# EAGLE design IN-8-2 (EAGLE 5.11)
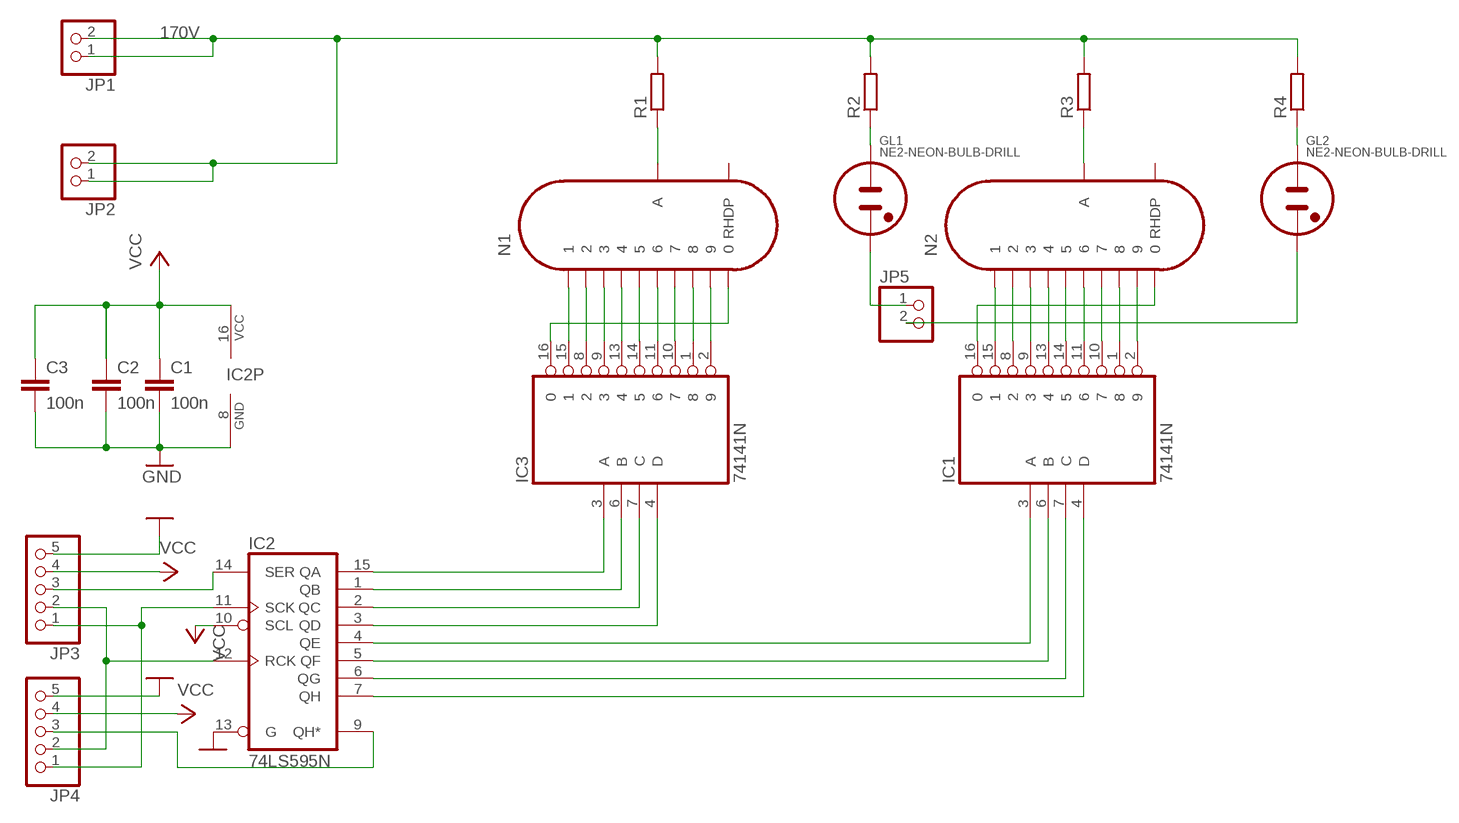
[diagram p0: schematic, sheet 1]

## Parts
C1  100n  C-EU025_050-025X075  [C025_050-025X075]
C2  100n  C-EU025_050-025X075  [C025_050-025X075]
C3  100n  C-EU025_050-025X075  [C025_050-025X075]
GL1  NE2-NEON-BULB-DRILL  [NE2-NEON-BULB-DRILL]
GL2  NE2-NEON-BULB-DRILL  [NE2-NEON-BULB-DRILL]
IC1  74141N  [DIL16]
IC2  74LS595N  [DIL16]
IC3  74141N  [DIL16]
JP1  PINHD-1X2  [1X02]
JP2  PINHD-1X2  [1X02]
JP3  PINHD-1X5  [1X05]
JP4  PINHD-1X5  [1X05]
JP5  PINHD-1X2  [1X02]
N1  IN-8-2  [IN-8-2]
N2  IN-8-2  [IN-8-2]
R1  R-EU_0207/12  [0207/12]
R2  R-EU_0207/12  [0207/12]
R3  R-EU_0207/12  [0207/12]
R4  R-EU_0207/12  [0207/12]

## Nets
170V: JP1.1 JP1.2 JP2.1 JP2.2 R1.2 R2.2 R3.2 R4.2
GND: C1.2 C2.2 C3.2 IC2.8(GND) IC2.13(G) JP3.5 JP4.5
N$1: IC3.15 N1.1
N$2: IC3.8 N1.2
N$3: IC3.9 N1.3
N$4: IC3.13 N1.4
N$5: IC3.14 N1.5
N$6: IC3.11 N1.6
N$7: IC3.10 N1.7
N$8: IC3.1 N1.8
N$9: IC3.2 N1.9
N$10: IC3.16 N1.0
N$11: N1.A R1.1
N$12: GL1.1(A) R2.1
N$13: IC1.15 N2.1
N$15: IC1.8 N2.2
N$16: IC1.9 N2.3
N$17: IC1.13 N2.4
N$18: IC1.14 N2.5
N$19: IC1.11 N2.6
N$20: IC1.10 N2.7
N$21: IC1.1 N2.8
N$22: IC1.2 N2.9
N$23: IC1.16 N2.0
N$25: N2.A R3.1
N$26: GL2.1(A) R4.1
N$27: GL1.2(A1) JP5.1
N$28: IC2.15(QA) IC3.3(A)
N$29: IC2.1(QB) IC3.6(B)
N$30: IC2.2(QC) IC3.7(C)
N$31: IC2.3(QD) IC3.4(D)
N$32: IC1.3(A) IC2.4(QE)
N$33: IC1.6(B) IC2.5(QF)
N$34: IC1.7(C) IC2.6(QG)
N$35: IC1.4(D) IC2.7(QH)
N$37: GL2.2(A1) JP5.2
N$40: IC2.14(SER) JP3.3
N$41: IC2.11(SCK) JP3.1 JP4.1
N$42: IC2.12(RCK) JP3.2 JP4.2
N$45: IC2.9(QH*) JP4.3
VCC: C1.1 C2.1 C3.1 IC2.10(SCL) IC2.16(VCC) JP3.4 JP4.4
Unconnected: N1..(RHDP) N2..(RHDP)

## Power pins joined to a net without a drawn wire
GND: IC1.12(GND) IC3.12(GND)
VCC: IC1.5(VCC) IC3.5(VCC)

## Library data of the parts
C1-C3 = resistor:C-EU: CAPACITOR, European symbol
GL1 GL2 = nixies:NE2-NEON-BULB: Neon indicator (wire connection)
IC1 IC3 = 74xx-eu:74*141: BCD to decimal DECODER/DRIVER
IC2 = 74xx-us:74*595: 8-bit SHIFT REGISTER, output latch
JP1 JP2 JP5 = pinhead:PINHD-1X2: PIN HEADER
JP3 JP4 = pinhead:PINHD-1X5: PIN HEADER
N1 N2 = russian-nixies:IN-8-2: IN-8-2: medium numeric frontview nixie tube
R1-R4 = resistor:R-EU_: RESISTOR, European symbol

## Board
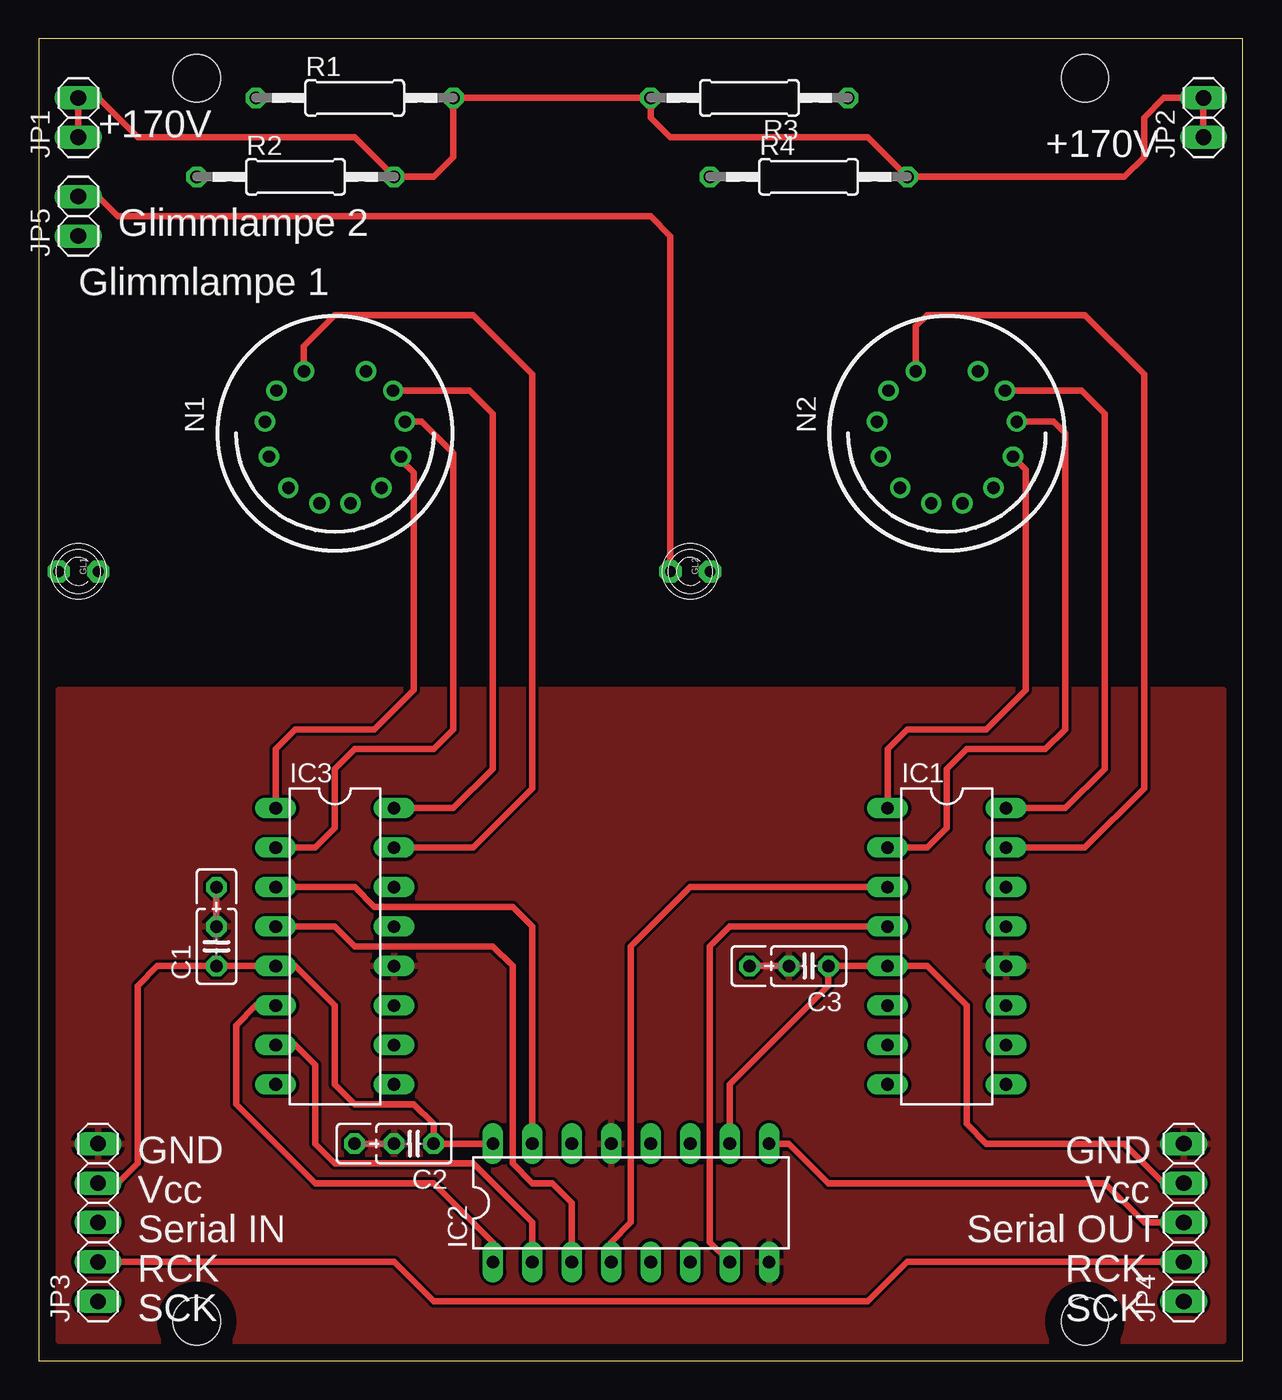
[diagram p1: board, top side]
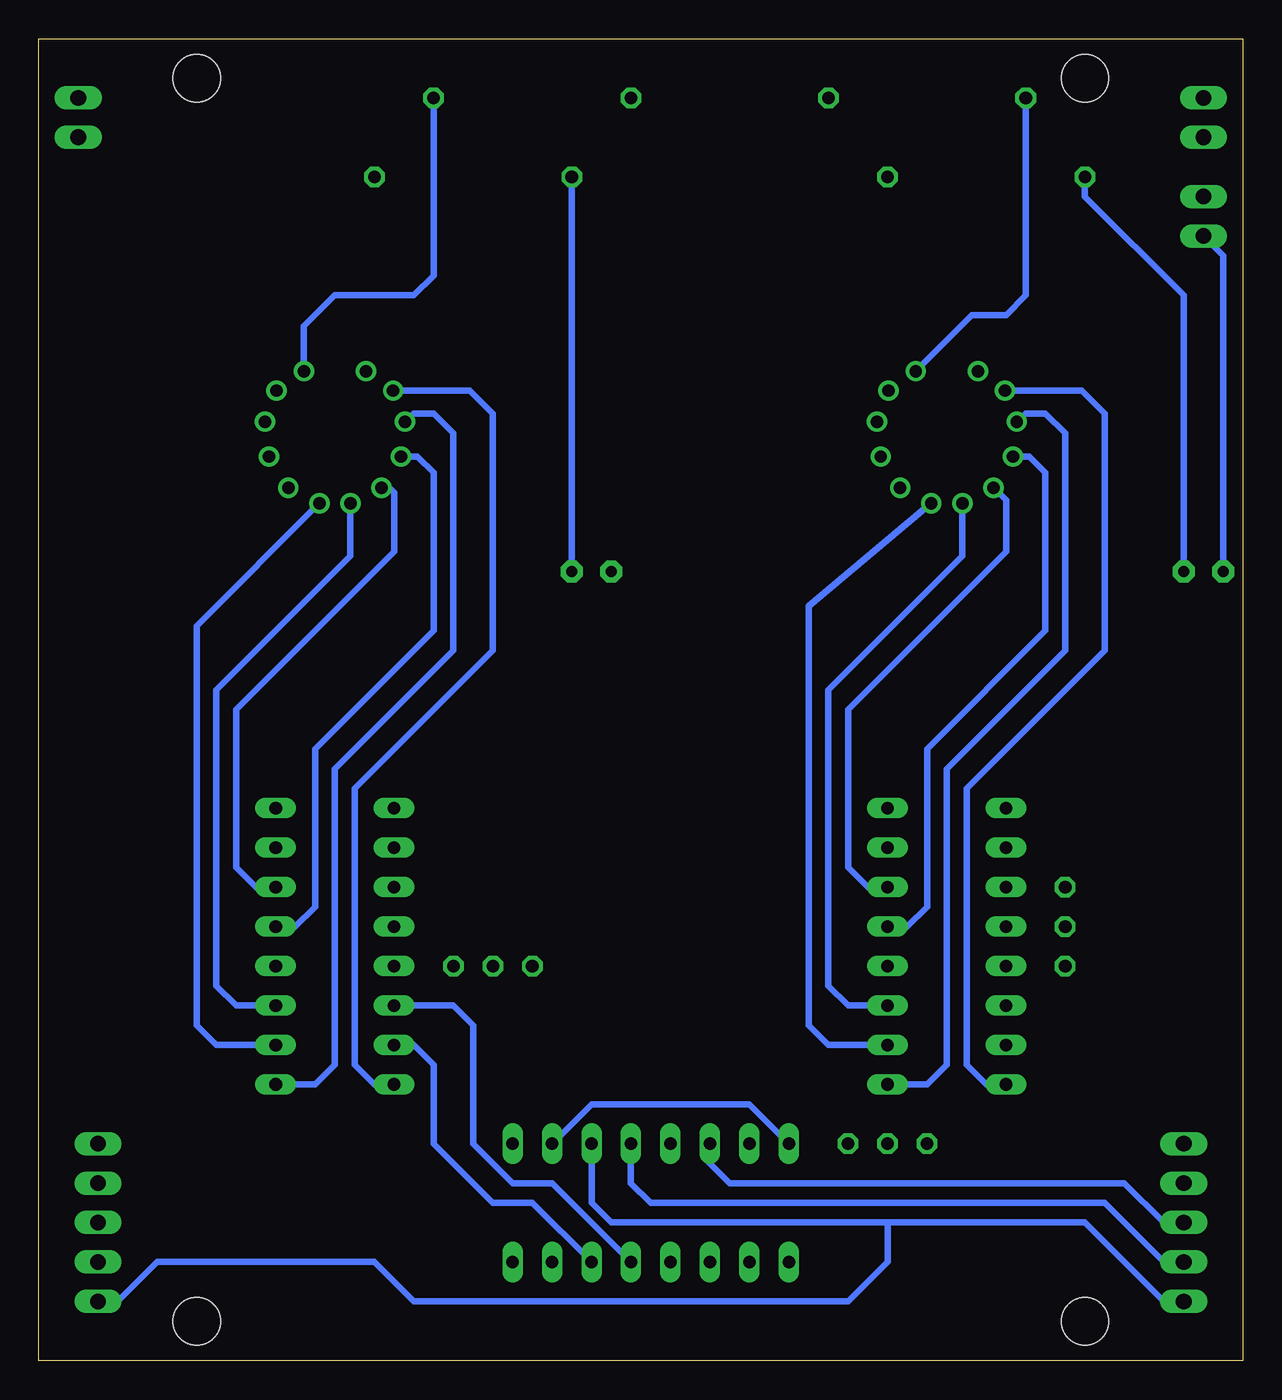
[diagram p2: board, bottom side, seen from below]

Size 77.47 x 85.08 mm. Coordinates in mm from the lower left corner, seen from the top.
Outline: 0,0 77.47,0 77.47,85.08 0,85.08 0,0
Copper layers (1*16): Top 0.035mm / dielectric 1.5mm / Bottom 0.035mm
Design rules "default": minimum track width 10mil, minimum drill 24mil, track to track 8mil, track to pad 8mil, pad to pad 8mil, via to via 8mil, smd to smd 8mil, copper to edge 40mil, drill to drill 8mil, minimum pad ring 10mil, minimum via ring 8mil, stop-mask expansion 4mil, vias tented up to drill 0mil, thermal gap 10mil
Holes 3.05 mm at 10.16,82.55 67.31,82.55 67.31,2.54 10.16,2.54

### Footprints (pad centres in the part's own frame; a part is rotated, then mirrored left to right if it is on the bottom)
C025_050-025X075 = drill 0.813 octagon: 1 -1.27,0; 2 1.27,0; 3 3.81,0
NE2-NEON-BULB-DRILL = drill 0.7 pad 1.422 octagon: 1 0,1.27; 2 0,-1.27
DIL16 = drill 0.813 long: 1 -8.89,-3.81; 2 -6.35,-3.81; 3 -3.81,-3.81; 4 -1.27,-3.81; 5 1.27,-3.81; 6 3.81,-3.81; 7 6.35,-3.81; 8 8.89,-3.81; 9 8.89,3.81; 10 6.35,3.81; 11 3.81,3.81; 12 1.27,3.81; 13 -1.27,3.81; 14 -3.81,3.81; 15 -6.35,3.81; 16 -8.89,3.81
1X02 = drill 1.016 long: 1 -1.27,0; 2 1.27,0
1X05 = drill 1.016 long: 1 -5.08,0; 2 -2.54,0; 3 0,0; 4 2.54,0; 5 5.08,0
IN-8-2 = drill 0.8 round: 0 -3.75,-2.75; 1 2,-4; 2 3.75,-2.75; 3 4.5,-0.75; 4 4.25,1.5; 5 3,3.5; 6 1,4.5; 7 -1,4.5; 8 -4.25,1.5; 9 -4.5,-0.75; . -3,3.5; A -2,-4
0207/12 = drill 0.813 octagon: 1 -6.35,0; 2 6.35,0

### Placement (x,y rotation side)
C1  11.43,26.67 90 top
C2  24.13,13.97 180 top
C3  49.53,25.4 180 top
GL1  2.54,50.8 270 top
GL2  41.91,50.8 270 top
IC1  58.42,26.67 270 top
IC2  38.1,10.16 0 top
IC3  19.05,26.67 270 top
JP1  2.54,80.01 90 top
JP2  74.93,80.01 90 top
JP3  3.81,8.89 90 top
JP4  73.66,8.89 90 top
JP5  2.54,73.66 90 top
N1  19.05,59.69 180 top
N2  58.42,59.69 180 top
R1  20.32,81.28 0 top
R2  16.51,76.2 0 top
R3  45.72,81.28 180 top
R4  49.53,76.2 0 top

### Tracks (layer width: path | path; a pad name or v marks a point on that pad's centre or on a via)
170V
  Top 0.406: JP1.1 JP1.2 3.81,81.28 6.35,78.74 20.32,78.74 R2.2 25.4,76.2 26.67,77.47 R1.2 R3.2 39.37,80.01 40.64,78.74 53.34,78.74 R4.2 69.85,76.2 71.12,77.47 71.12,80.01 72.39,81.28 JP2.2 JP2.1
GND
  Top 0.406: 20.32,13.97 C2.2 | 45.72,25.4 C3.2 | C1.2 11.43,30.48
  pour Top: 1.27,43.18 76.2,43.18 76.2,1.27 1.27,1.27
N$1
  Top 0.406: N1.1 17.05,65.31 19.05,67.31 27.94,67.31 31.75,63.5 31.75,36.83 27.94,33.02 IC3.15
N$2
  Bottom 0.406: IC3.8 16.51,17.78 17.78,19.05 17.78,36.83 8.89,45.72 8.89,60.96 10.37,62.44 N1.2
N$3
  Bottom 0.406: IC3.9 20.32,17.78 19.05,19.05 19.05,38.1 11.43,45.72 11.43,59.69 12.7,60.96 13.97,60.96 14.49,60.44 N1.3
N$4
  Bottom 0.406: IC3.13 21.59,27.94 20.32,29.21 20.32,39.37 12.7,46.99 12.7,57.15 13.74,58.19 N1.4
N$5
  Bottom 0.406: IC3.14 24.13,30.48 25.4,31.75 25.4,41.91 15.24,52.07 15.24,55.38 N1.5
N$6
  Bottom 0.406: N1.6 18.05,51.8 26.67,43.18 26.67,24.13 25.4,22.86 IC3.11
N$7
  Bottom 0.406: IC3.10 26.67,20.32 27.94,21.59 27.94,48.57 N1.7
N$8
  Top 0.406: N1.8 23.3,57.98 24.13,57.15 24.13,43.18 21.59,40.64 16.51,40.64 15.24,39.37 IC3.1
N$9
  Top 0.406: N1.9 24.65,60.44 26.67,58.42 26.67,40.64 25.4,39.37 20.32,39.37 19.05,38.1 19.05,34.29 17.78,33.02 IC3.2
N$10
  Top 0.406: IC3.16 26.67,35.56 29.21,38.1 29.21,60.96 27.73,62.44 N1.0
N$11
  Bottom 0.406: R1.1 13.97,68.58 15.24,67.31 17.43,67.31 N1.A
N$12
  Bottom 0.406: R2.1 10.16,74.93 3.81,68.58 GL1.1
N$13
  Top 0.406: IC1.15 67.31,33.02 71.12,36.83 71.12,63.5 67.31,67.31 57.15,67.31 56.42,66.58 N2.1
N$15
  Bottom 0.406: IC1.8 55.88,17.78 57.15,19.05 57.15,36.83 48.26,45.72 48.26,60.96 49.74,62.44 N2.2
N$16
  Bottom 0.406: IC1.9 59.69,17.78 58.42,19.05 58.42,38.1 50.8,45.72 50.8,59.69 52.07,60.96 53.34,60.96 53.86,60.44 N2.3
N$17
  Bottom 0.406: IC1.13 60.96,27.94 59.69,29.21 59.69,39.37 52.07,46.99 52.07,57.15 53.11,58.19 N2.4
N$18
  Bottom 0.406: IC1.14 63.5,30.48 64.77,31.75 64.77,41.91 54.61,52.07 54.61,55.88 54.92,56.19 N2.5
N$19
  Bottom 0.406: IC1.11 64.77,22.86 66.04,24.13 66.04,43.18 57.42,51.8 N2.6
N$20
  Bottom 0.406: IC1.10 66.04,20.32 67.31,21.59 67.31,47.3 N2.7
N$21
  Top 0.406: IC1.1 54.61,39.37 55.88,40.64 60.96,40.64 63.5,43.18 63.5,57.36 N2.8
N$22
  Top 0.406: IC1.2 57.15,33.02 58.42,34.29 58.42,38.1 59.69,39.37 64.77,39.37 66.04,40.64 66.04,59.69 65.29,60.44 N2.9
N$23
  Top 0.406: IC1.16 66.04,35.56 68.58,38.1 68.58,60.96 67.1,62.44 N2.0
N$25
  Bottom 0.406: R3.1 52.07,69.85 53.34,68.58 58.42,68.58 60.42,66.58 N2.A
N$26
  Bottom 0.406: GL2.1 R4.1
N$27
  Bottom 0.406: GL1.2 1.27,71.12 JP5.1
N$28
  Top 0.406: IC2.15 31.75,27.94 30.48,29.21 21.59,29.21 20.32,30.48 IC3.3
N$29
  Top 0.406: IC2.1 29.21,7.62 25.4,11.43 17.78,11.43 12.7,16.51 12.7,21.59 13.97,22.86 IC3.6
N$30
  Top 0.406: IC2.2 31.75,8.89 27.94,12.7 19.05,12.7 17.78,13.97 17.78,19.05 16.51,20.32 IC3.7
N$31
  Top 0.406: IC3.4 19.05,27.94 20.32,26.67 29.21,26.67 30.48,25.4 30.48,12.7 31.75,11.43 33.02,11.43 34.29,10.16 IC2.3
N$32
  Top 0.406: IC2.4 36.83,7.62 38.1,8.89 38.1,26.67 41.91,30.48 IC1.3
N$33
  Bottom 0.406: IC2.5 44.45,11.43 46.99,11.43 49.53,13.97 49.53,21.59 50.8,22.86 IC1.6
N$34
  Bottom 0.406: IC2.6 45.72,10.16 48.26,10.16 52.07,13.97 52.07,19.05 53.34,20.32 IC1.7
N$35
  Top 0.406: IC1.4 44.45,27.94 43.18,26.67 43.18,7.62 IC2.7
N$37
  Top 0.406: JP5.2 3.81,74.93 5.08,73.66 39.37,73.66 40.64,72.39 GL2.2
N$40
  Bottom 0.406: JP3.3 5.08,8.89 7.62,11.43 33.02,11.43 34.29,12.7 IC2.14
N$41
  Bottom 0.406: JP3.1 5.08,3.81 10.16,8.89 22.86,8.89 | 22.86,8.89 40.64,8.89 41.91,10.16 IC2.11 | JP4.1 72.39,3.81 69.85,6.35 55.88,6.35 53.34,3.81 25.4,3.81 22.86,6.35 22.86,8.89
N$42
  Top 0.406: 72.39,6.35 JP4.2 55.88,6.35 53.34,3.81 25.4,3.81 22.86,6.35 JP3.2
  Bottom 0.406: JP3.2 5.08,6.35 8.89,10.16 38.1,10.16 39.37,11.43 IC2.12
N$45
  Top 0.406: IC2.9 48.26,13.97 50.8,11.43 68.58,11.43 71.12,8.89 JP4.3
VCC
  Top 0.406: JP3.4 5.08,11.43 6.35,12.7 6.35,24.13 7.62,25.4 C1.1 IC3.5 16.51,25.4 19.05,22.86 19.05,17.78 20.32,16.51 24.13,16.51 25.4,15.24 C2.1 IC2.16 | JP4.4 72.39,11.43 69.85,13.97 60.96,13.97 59.69,15.24 59.69,22.86 57.15,25.4 IC1.5 C3.1 50.8,24.13 44.45,17.78 IC2.10
  Bottom 0.406: IC2.16 31.75,16.51 41.91,16.51 IC2.10

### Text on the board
tPlace: +170V | +170V | Glimmlampe 2 | Glimmlampe 1 | GND | GND | Vcc | Vcc | Serial IN | Serial OUT | RCK | RCK | SCK | SCK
